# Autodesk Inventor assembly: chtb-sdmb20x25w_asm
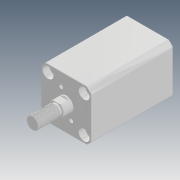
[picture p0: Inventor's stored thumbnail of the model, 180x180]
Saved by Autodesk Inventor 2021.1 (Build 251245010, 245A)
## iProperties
Company: Microsoft
Created: 2018-05
Part Number: chtb-sdmb20x25w_asm
Description: STEP AP214
Document SubType Name: Assembly
Designer: user
Title: chtb-sdmb20x25w_asm.STEP
Author: Windows
Revision Number: ÈÎºÎ
Sending System: SolidWorks 2015
Preprocessor: SwSTEP 2.0
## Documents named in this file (4)
- D:\Vault_2016\Projekty\Clamptek\Hydraulic\CHTB\CHTB-20\Inventor\CHTB-SDMB20x25W\chtb-sdmb20x25w_asm.iam
- D:\Vault_2016\Projekty\Clamptek\Hydraulic\CHTB\CHTB-20\Inventor\CHTB-SDMB20x25W\CHTB-SDMB20X25NBT.ipt
- D:\Vault_2016\Projekty\Clamptek\Hydraulic\CHTB\CHTB-20\Inventor\CHTB-SDMB20x25W\CHTB-SDMB20X25WHSG.ipt
- D:\Vault_2016\Projekty\Clamptek\Hydraulic\CHTB\CHTB-20\Inventor\CHTB-SDMB20x25W\QG_3.ipt
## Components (3 placed, 3 different names)
1. CHTB-SDMB20X25NBT_1
2. CHTB-SDMB20X25WHSG_2
3. QG_3_3
